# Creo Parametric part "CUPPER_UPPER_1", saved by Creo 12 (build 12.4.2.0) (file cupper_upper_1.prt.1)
Units: Custom; MM, KILOGRAM, SECS

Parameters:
  PTC_WM_ITERATION = "0"
  PTC_WM_VERSION = "-.0"
  PTC_WM_LIFECYCLE_STATE = "In Work"
  PTC_WM_LIFECYCLE = "MO_CADDocument"
  PTC_WM_CREATED_BY = "Maximilian Roepper (Z0017RMS: MO)"
  PTC_WM_CREATED_ON = "18-Sep-26 11:36:42 AM"
  PTC_WM_MODIFIED_BY = "Maximilian Roepper (Z0017RMS: MO)"
  PTC_WM_MODIFIED_ON = "18-Sep-26 11:36:46 AM"
  PDMLINKNUMBER = "PDM000071455123"
  PTC_WM_NAME = "cupper_upper_1.prt"
  PTC_WM_NUMBER = "PDM000071455123"

Other parameters: WEIGHT, WEIGHT_FACTOR, WEIGHT_ADD, _MASS_TEMP, _DIFF_TEMP, MC_ERRORS, SUPPLIER

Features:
  1. coordinate system
  2. datum plane "PRT_YZ"
  3. datum plane "PRT_XY"
  4. datum plane "PRT_XZ"
  5. coordinate system
  6. datum axis
  7. datum axis
  8. datum axis
  9. coordinate system
  10. imported feature
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
Other named items: PRT, SIEMENS_MO, DRW_VIEW_ORG, PRT_X, PRT_Y, PRT_Z, CS0, ROUGH_GROB

Layers: 00_STD_CSYS-KSYS, 01_STD_PLANES-EBENEN, 02_STD_AXES-ACHSEN, 03_STD_CSYS-KSYS, 24_IMPORT_FEAT-IMPORT_KE

Surfaces: 184 plane, 72 cylinder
